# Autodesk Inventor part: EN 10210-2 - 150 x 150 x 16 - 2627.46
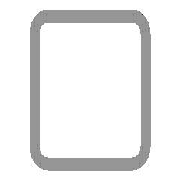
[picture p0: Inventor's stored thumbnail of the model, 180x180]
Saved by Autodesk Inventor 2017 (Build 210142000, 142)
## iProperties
Created: 2016-02
Part Number: EN 10210-2 - 150 x 150 x 16 - 2627.46
Material: Steel, Mild
Description: Tube
Document SubType Name: Modeling
Standard: DIN
Designer: iusti
Standard Revision: 2006-07
Standards Organization: DIN
Language: en-US
Size Designation: 150 x 150 x 16
Categories: <MemberInstance><Categories><Category DisplayName="Structural Shapes" InternalName="089c4875-fa83-4c05-b084-43b9cc11f5ed" Mnemonic="GRDR"><CategoryParameter Dis
Stock Number: 150 x 150 x 16
Density: 7.85 g/cm^3
Appearance: Semi-Polished
IsCustomPart: 1
_CCFamilyMember: 70
_CCFamilyDisplayName: DIN EN 10210-2 (Square) - Tube — Sizes in parentheses have been withdrawn
_FrameMemberDoc: Frame Member File
_Version: 15.0.0
_GetPNFromCC: 1
Author: iusti
G_L: 2627.460 mm
G_W: 150.000 mm
G_H: 150.000 mm
+1C1875EB-09B4-4BC1-A3F9-F1E22132A380+CUTDETAIL1: Cut
+973DBC56-8C91-4BBB-AADC-B661641204C8+CUTDETAIL2: Cut
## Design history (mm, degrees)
node "Start plane"
node "End plane"
sketch "Sketch"
  geometry: L1 (-75, -51)-(-75, 51); L2 (-51, 75)-(51, 75); L3 (75, 51)-(75, -51); L4 (51, -75)-(-51, -75); L5 (-43, 59)-(43, 59); L6 (59, 43)-(59, -43); L7 (43, -59)-(-43, -59); L8 (-59, -43)-(-59, 43); L9 (0, 111.959)-(0, -111.959) reference; L10 (-111.959, 0)-(111.959, 0) reference; A1 r 24 centre (-51, -51) between (-75, -51) and (-51, -75); A2 r 24 centre (-51, 51) between (-51, 75) and (-75, 51); A3 r 24 centre (51, 51) between (75, 51) and (51, 75); A4 r 24 centre (51, -51) between (51, -75) and (75, -51); A5 r 16 centre (-43, -43) between (-59, -43) and (-43, -59); A6 r 16 centre (-43, 43) between (-43, 59) and (-59, 43); A7 r 16 centre (43, 43) between (59, 43) and (43, 59); A8 r 16 centre (43, -43) between (43, -59) and (59, -43)
  constraints: 16 end point, 16 point on circle, 16 tangent, 8 centre point, 6 equal radius, 4 parallel, 2 perpendicular, 2 other
  dimensions: "d7" = 24 radius of A1 (= G_IR); "d10" = 150 distance between parallel lines of L2 L4 (= G_H); "d11" = 150 distance between parallel lines of L1 L3 (= G_W); "d12" = 16 distance between parallel lines of L3 L6 (= G_T); "d15" = 75 distance between parallel lines of L2 L10 (= 0.5 x d10); "d16" = 75 distance between parallel lines of L9 L3 (= 0.5 x d11); "d19" = 16 radius of A5 (= G_T); "d20" = 16 distance between parallel lines of L4 L7 (= G_T)
extrude "Body" new body sketch "Sketch" stored distance "d3" = 2627.46034 (= G_L); taper "d4" = 0 deg
node "Driven Length"
  sketch "Sketch3"
    geometry: L1 (0, 0)-(10, 0) reference
    constraints: 2 end point, 1 horizontal
  workplane "Work Plane3"
  sketch "Sketch4"
    geometry: L1 (-2, 35.842)-(12, 35.842) reference; L2 (-2, 2663.303)-(12, 2663.303) reference
    dimensions: "d18" = 2627.46034 distance between parallel lines of L1 L2 (derived)
workplane "Work Plane4"
split "Split1"
workplane "Work Plane5"
split "Split2"
body "Solid1"
other parameters: "G_W" = 150 [user parameter; used in 1 equation term], "G_H" = 150 [user parameter; used in 1 equation term], "G_T" = 16 [user parameter; used in 3 equation terms], "G_IR" = 24 [user parameter; used in 1 equation term], "G_L" = 2627.46034 (= d18) [user parameter; used in 1 equation term], "G_OFFSET_START" = -35.84222 [user parameter; used in 1 equation term], "G_OFFSET_END" = 92.90179 [user parameter; used in 1 equation term], "d13" = 35.84222 (= -G_OFFSET_START), "d14" = 2663.30256 (= G_OFFSET_END + B_L), "B_L" = 2570.40077 [user parameter; used in 1 equation term], "d17" = 90 deg
